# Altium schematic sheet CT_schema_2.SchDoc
size 528 x 483 mm
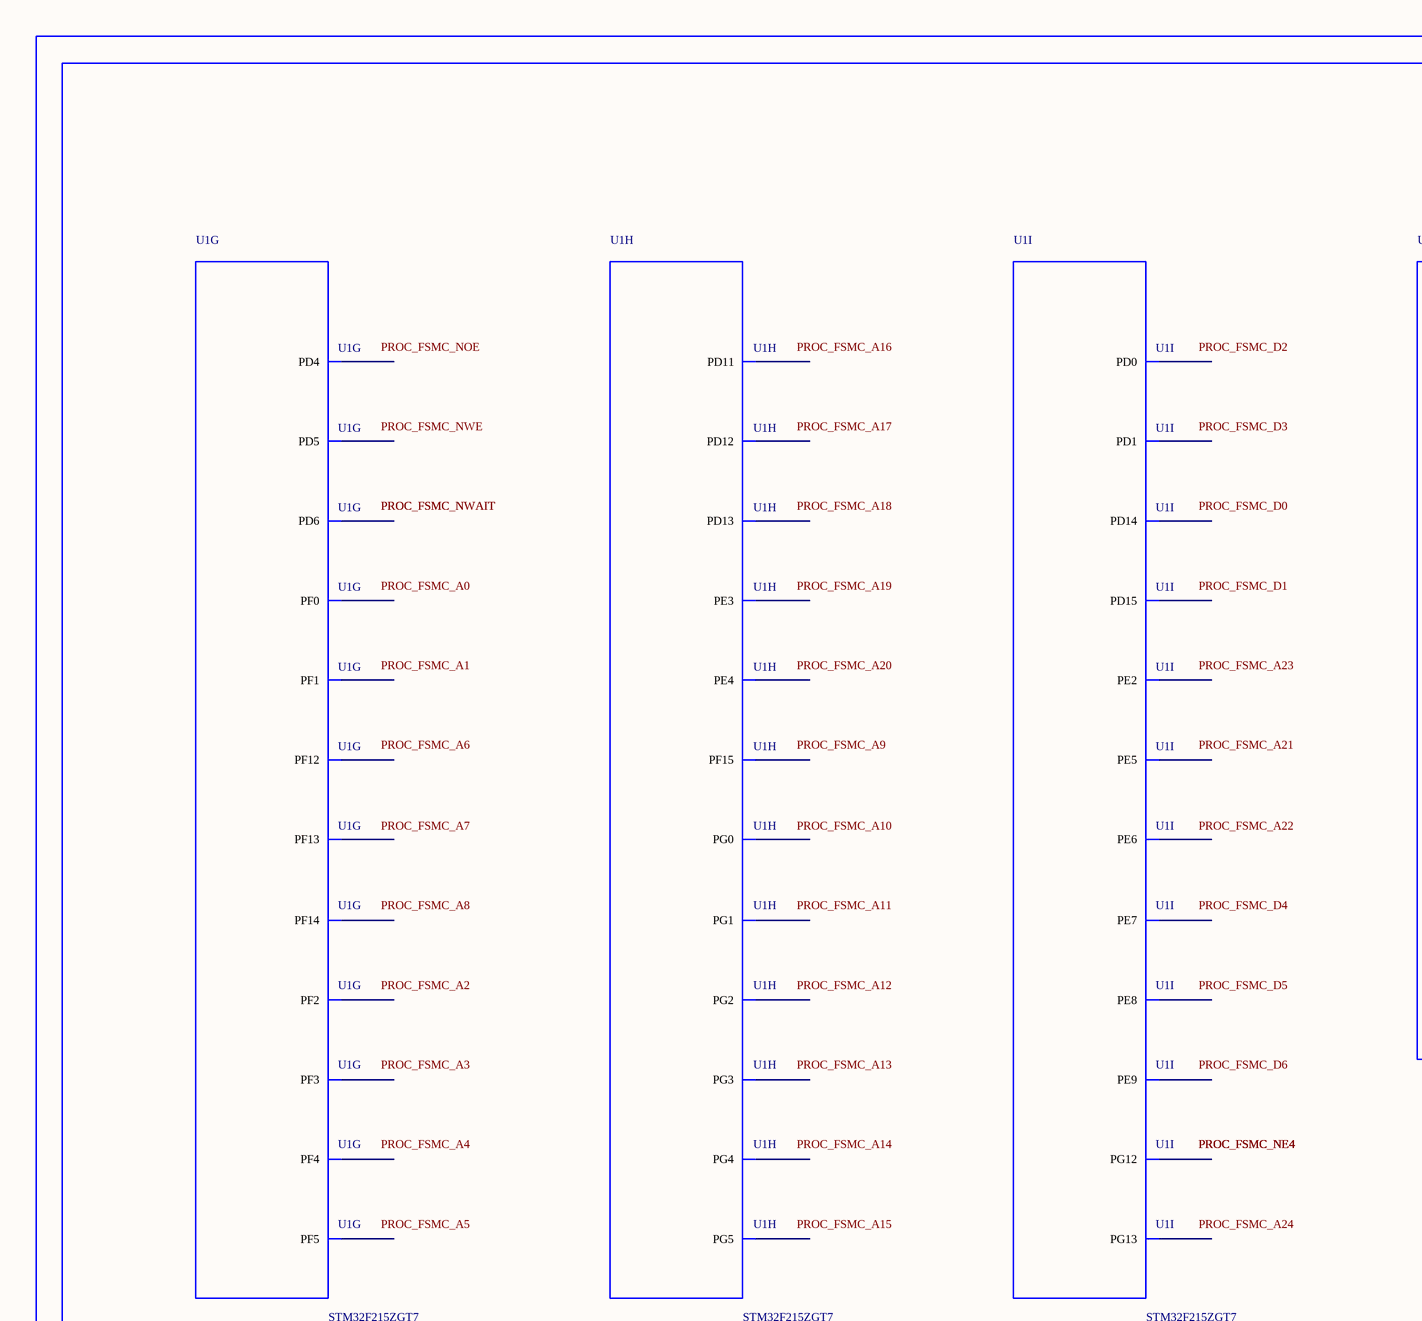
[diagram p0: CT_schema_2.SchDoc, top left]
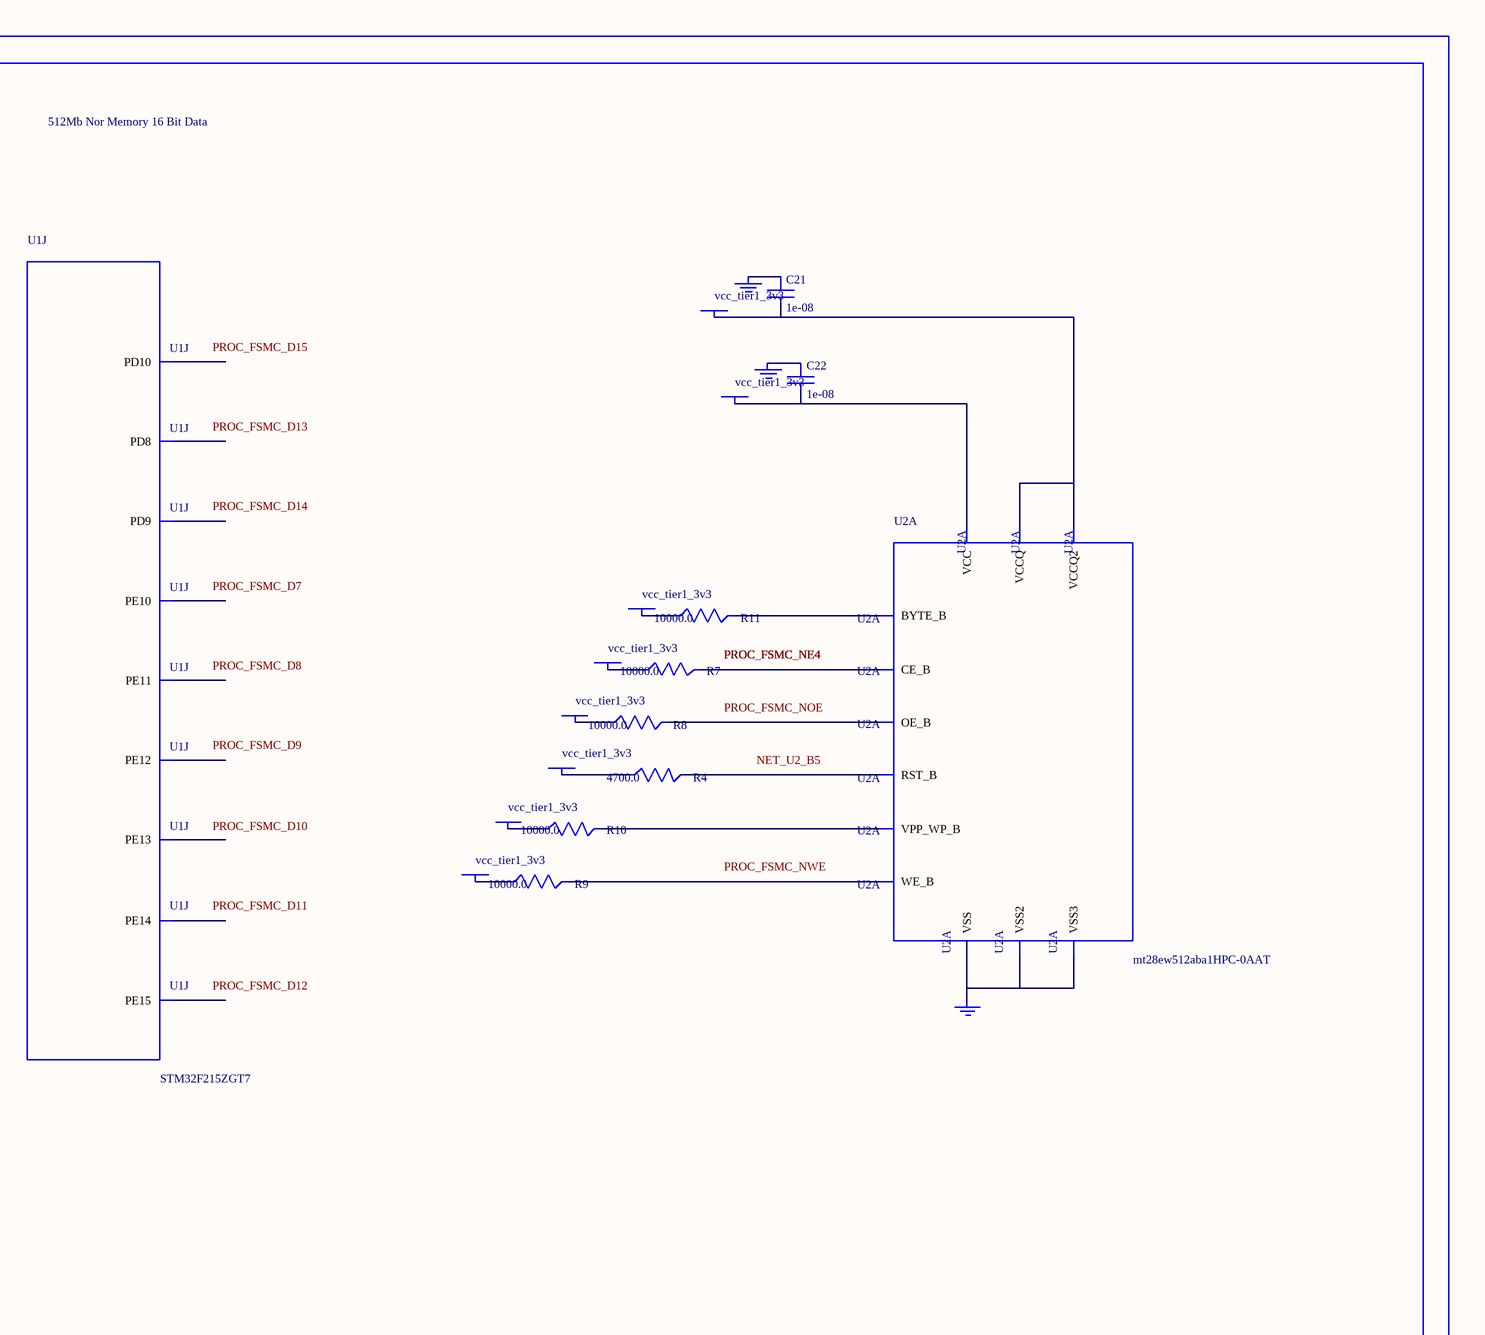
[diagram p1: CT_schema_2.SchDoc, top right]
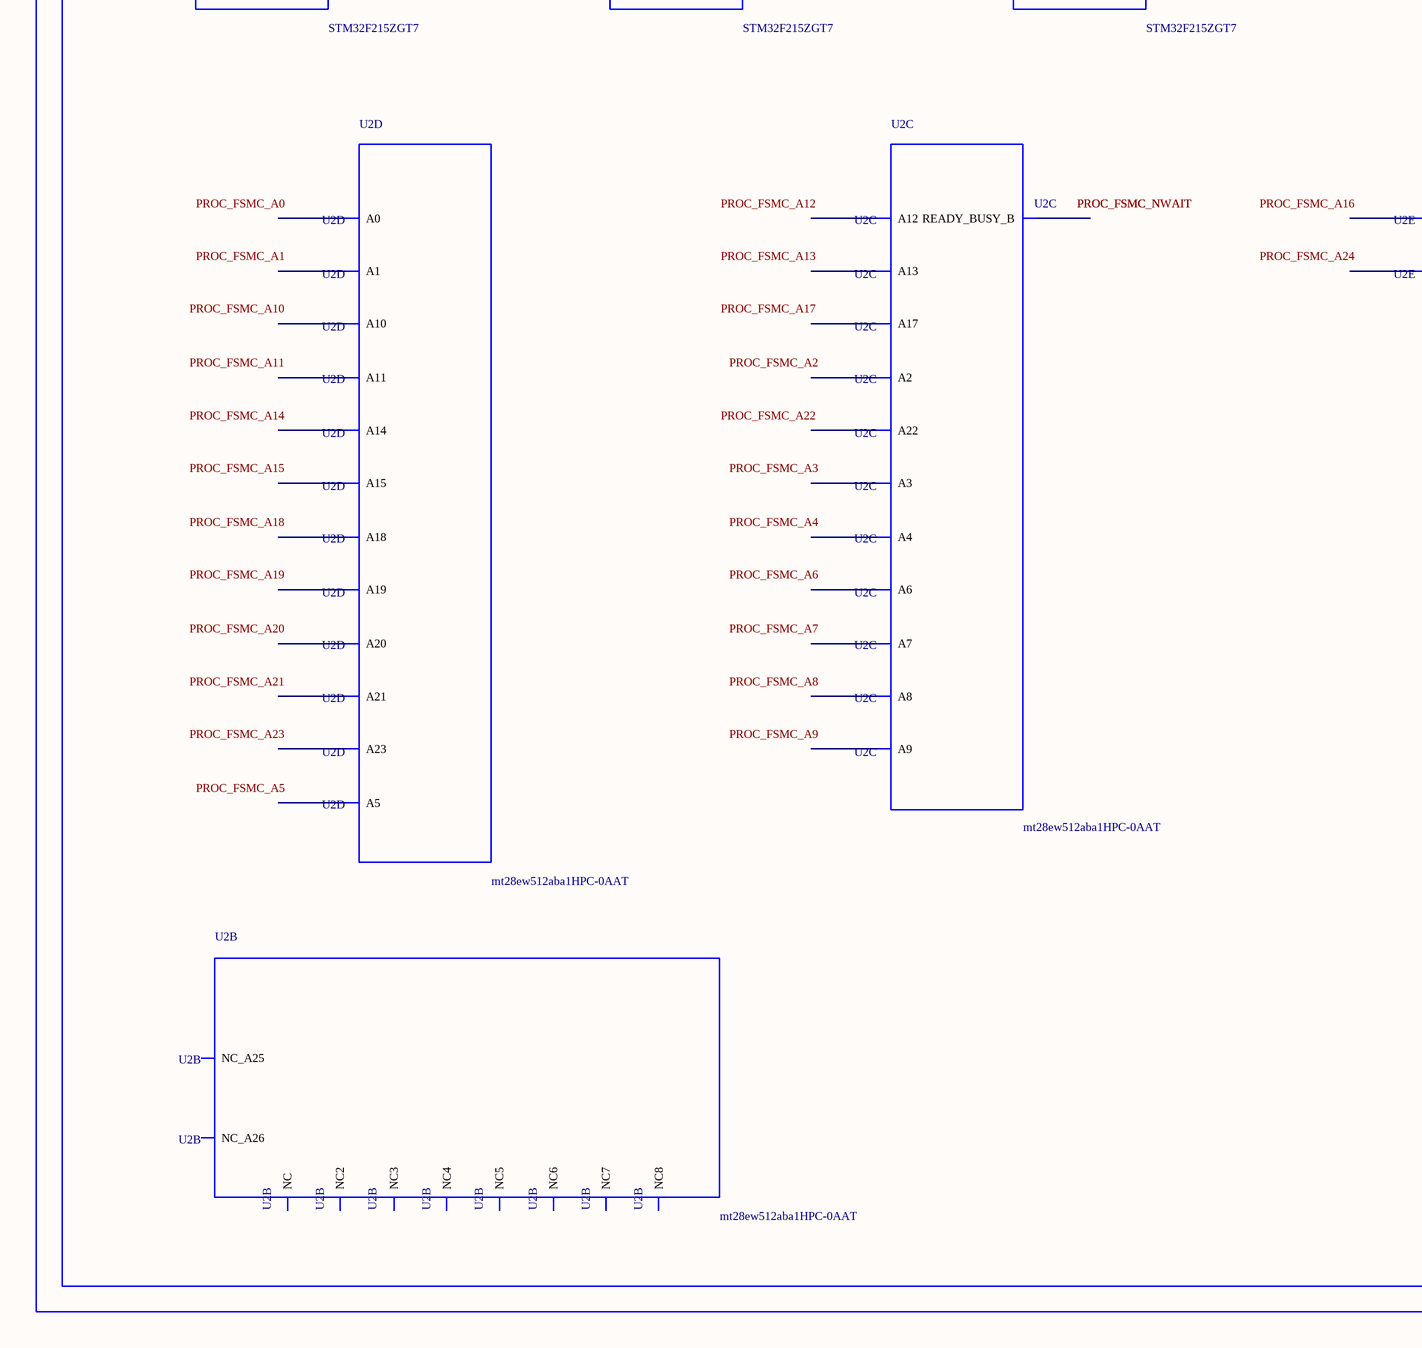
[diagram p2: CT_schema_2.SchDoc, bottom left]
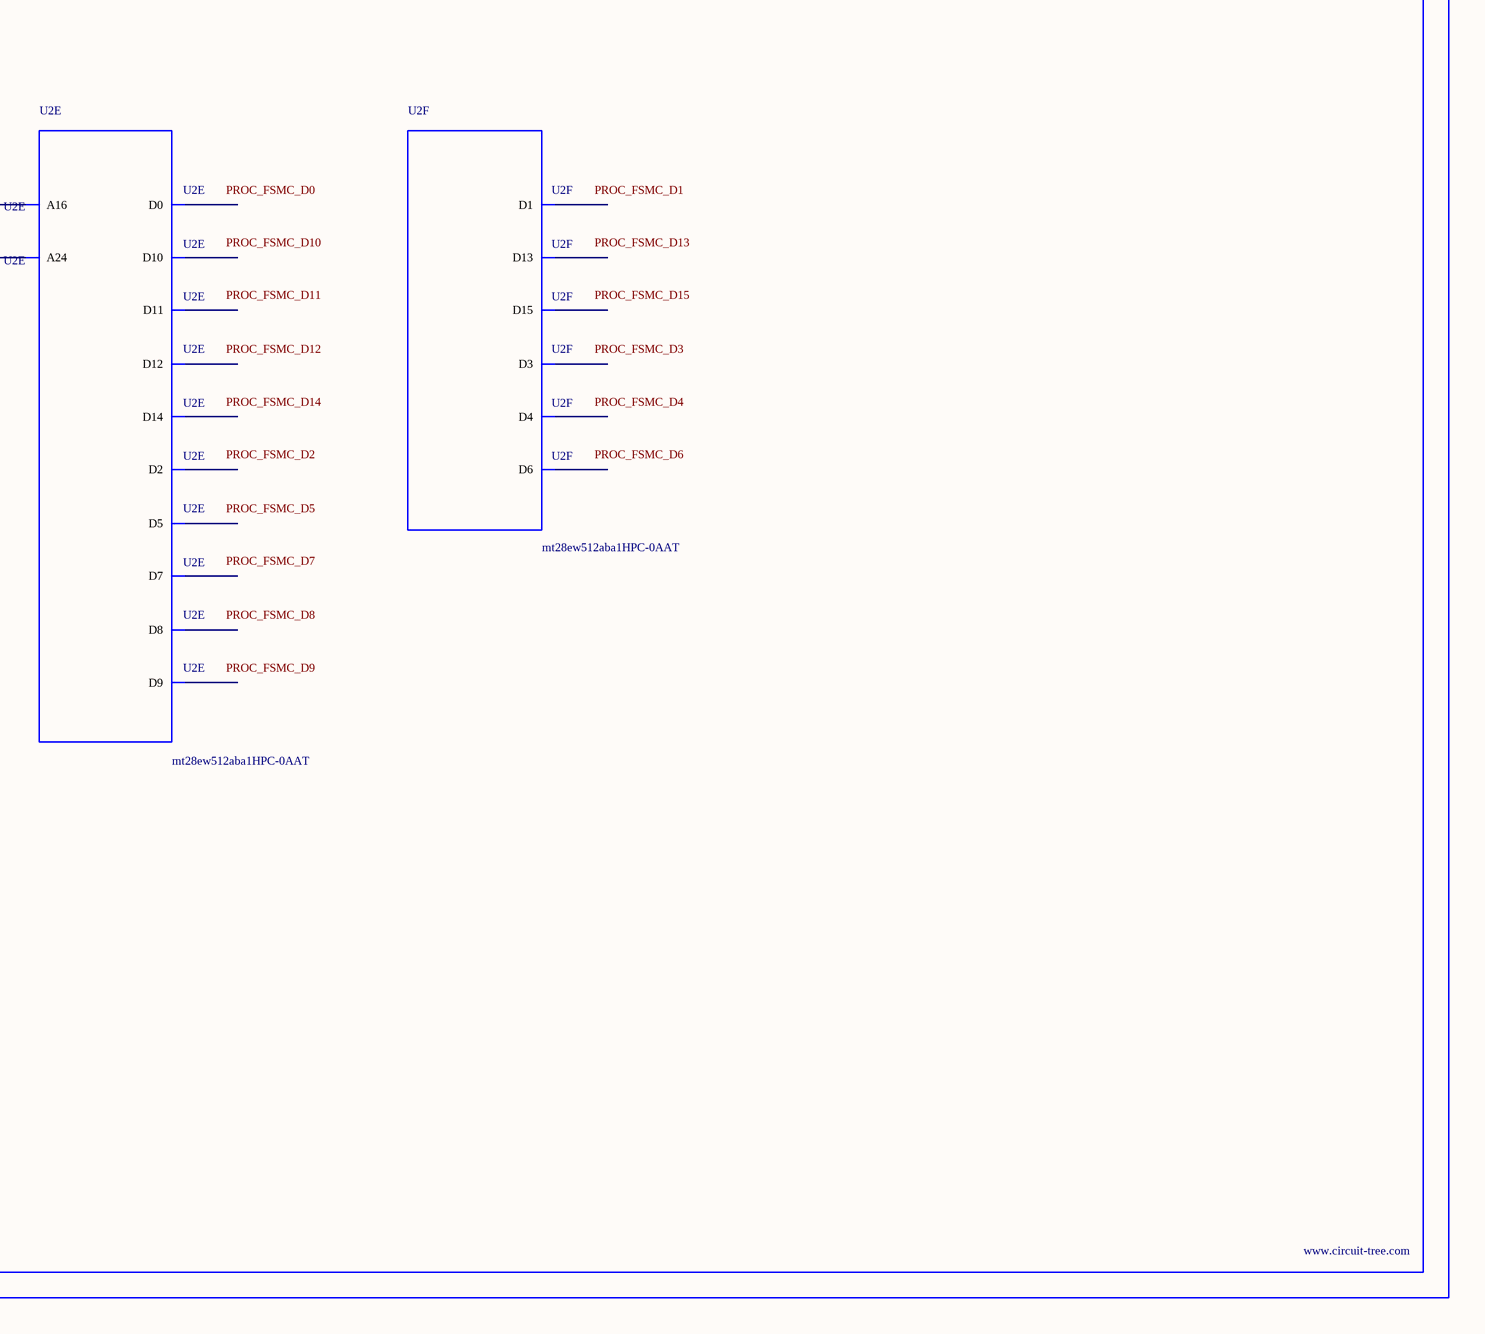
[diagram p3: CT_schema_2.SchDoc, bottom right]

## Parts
BORDER1  (no value)
C21  1e-08  [C0402]
C22  1e-08  [C0402]
GND_INSTANCE_1_0  (no value)
GND_INSTANCE_1_1  (no value)
GND_INSTANCE_1_2  (no value)
POWER_INSTANCE_1_0  vcc_tier1_3v3
POWER_INSTANCE_1_1  vcc_tier1_3v3
POWER_INSTANCE_1_2  vcc_tier1_3v3
POWER_INSTANCE_1_3  vcc_tier1_3v3
POWER_INSTANCE_1_4  vcc_tier1_3v3
POWER_INSTANCE_1_5  vcc_tier1_3v3
POWER_INSTANCE_1_6  vcc_tier1_3v3
POWER_INSTANCE_1_7  vcc_tier1_3v3
R4  4700.0  [R0603]
R7  10000.0  [R0603]
R8  10000.0  [R0603]
R9  10000.0  [R0603]
R10  10000.0  [R0603]
R11  10000.0  [R0603]
U1  STM32F215ZGT7  [LQFP144]  (parts G,H,I,J of 11)
U2  mt28ew512aba1HPC-0AAT  [LBGA-64]  (parts A,B,C,D,E,F of 6)

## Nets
NetC21_1: C21.1 GND_INSTANCE_1_0.0(GND)
NetC21_2: C21.2 POWER_INSTANCE_1_0.0(PWR) U2.D8(VCCQ) U2.F1(VCCQ2)
NetC22_1: C22.1 GND_INSTANCE_1_1.0(GND)
NetC22_2: C22.2 POWER_INSTANCE_1_1.0(PWR) U2.G5(VCC)
NetGND_INSTANCE_1_2_0: GND_INSTANCE_1_2.0(GND) U2.E8(VSS) U2.H2(VSS2) U2.H7(VSS3)
NetPOWER_INSTANCE_1_2_0: POWER_INSTANCE_1_2.0(PWR) R7.1
NetPOWER_INSTANCE_1_3_0: POWER_INSTANCE_1_3.0(PWR) R8.1
NetPOWER_INSTANCE_1_4_0: POWER_INSTANCE_1_4.0(PWR) R9.1
NetPOWER_INSTANCE_1_5_0: POWER_INSTANCE_1_5.0(PWR) R10.1
NetPOWER_INSTANCE_1_6_0: POWER_INSTANCE_1_6.0(PWR) R11.1
NetPOWER_INSTANCE_1_7_0: POWER_INSTANCE_1_7.0(PWR) R4.1
NetR4_2: R4.2 U2.B5(RST_B)
NetR7_2: R7.2 U2.F2(CE_B)
NetR8_2: R8.2 U2.G2(OE_B)
NetR9_2: R9.2 U2.A5(WE_B)
NetR10_2: R10.2 U2.B4(VPP_WP_B)
NetR11_2: R11.2 U2.F7(BYTE_B)

Not connected (* = marked no-connect by the designer): U1 1(PE2) 2(PE3) 3(PE4) 4(PE5) 5(PE6) 10(PF0) 11(PF1) 12(PF2) 13(PF3) 14(PF4) 15(PF5) 50(PF12) 53(PF13) 54(PF14) 55(PF15) 56(PG0) 57(PG1) 58(PE7) 59(PE8) 60(PE9) 63(PE10) 64(PE11) 65(PE12) 66(PE13) 67(PE14) 68(PE15) 77(PD8) 78(PD9) 79(PD10) 80(PD11) 81(PD12) 82(PD13) 85(PD14) 86(PD15) 87(PG2) 88(PG3) 89(PG4) 90(PG5) 114(PD0) 115(PD1) 118(PD4) 119(PD5) 122(PD6) 127(PG12) 128(PG13); U2 A1(NC) A2(A3) A3(A7) A4(READY_BUSY_B) A6(A9) A7(A13) A8(NC2) B1(NC_A26) B2(A4) B3(A17) B6(A8) B7(A12) B8(A22) C1(NC3) C2(A2) C3(A6) C4(A18) C5(A21) C6(A10) C7(A14) C8(A23) D1(NC4) D2(A1) D3(A5) D4(A20) D5(A19) D6(A11) D7(A15) E1(NC5) E2(A0) E3(D0) E4(D2) E5(D5) E6(D7) E7(A16) F3(D8) F4(D10) F5(D12) F6(D14) F8(A24) G1(NC6) G3(D9) G4(D11) G6(D13) G7(D15) G8(NC_A25) H1(NC7) H3(D1) H4(D3) H5(D4) H6(D6) H8(NC8)

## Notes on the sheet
- Labels drawn without touching a wire or pin: NET_U2_B5, PROC_FSMC_A0, PROC_FSMC_A1, PROC_FSMC_A2, PROC_FSMC_A3, PROC_FSMC_A4, PROC_FSMC_A5, PROC_FSMC_A6, PROC_FSMC_A7, PROC_FSMC_A8, PROC_FSMC_A9, PROC_FSMC_A10, PROC_FSMC_A11, PROC_FSMC_A12, PROC_FSMC_A13, PROC_FSMC_A14, PROC_FSMC_A15, PROC_FSMC_A16, PROC_FSMC_A17, PROC_FSMC_A18, PROC_FSMC_A19, PROC_FSMC_A20, PROC_FSMC_A21, PROC_FSMC_A22, PROC_FSMC_A23, PROC_FSMC_A24, PROC_FSMC_D0, PROC_FSMC_D1, PROC_FSMC_D2, PROC_FSMC_D3, PROC_FSMC_D4, PROC_FSMC_D5, PROC_FSMC_D6, PROC_FSMC_D7, PROC_FSMC_D8, PROC_FSMC_D9, PROC_FSMC_D10, PROC_FSMC_D11, PROC_FSMC_D12, PROC_FSMC_D13, PROC_FSMC_D14, PROC_FSMC_D15, PROC_FSMC_NOE, PROC_FSMC_NWE

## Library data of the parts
BORDER1 = BORDER_PAGE1
C21 C22 = C0402C103K3RAC
GND_INSTANCE_1_0-GND_INSTANCE_1_2 = GND
POWER_INSTANCE_1_0-POWER_INSTANCE_1_7 = PWR
R4 = RC0603JR-074K7L
R7-R11 = RC0603JR-0710KL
